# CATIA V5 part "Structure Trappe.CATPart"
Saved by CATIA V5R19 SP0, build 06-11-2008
Part number: Structure Trappe
Bounding box of the stored display mesh (mm): x -178.601 to 93.761, y -17.5 to 17.5, z -63.05 to 80.5
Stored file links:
  G:\EU_thinkMotion\CFAO_2010\St2M_groupe2\St2M_groupe2\csayed\csayed\csayed\Structure Trappe.CATPart
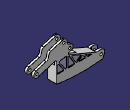
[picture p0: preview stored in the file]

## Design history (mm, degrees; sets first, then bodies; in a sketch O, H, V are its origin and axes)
Body1 (main body)
  Sketch1 on yz-plane, origin (0, 0, 0), H (0, 1, 0), V (0, 0, 1)
    line L1 (-17.5, 80.5) -> (-9.5, 80.5)
    line L2 (17.5, 80.5) -> (17.5, -63.05)
    line L3 (17.5, -63.05) -> (-17.5, -63.05)
    line L4 (-17.5, -63.05) -> (-17.5, 80.5)
    line L5 (9.5, 80.5) -> (9.5, 4.23)
    line L6 (9.5, 4.23) -> (-9.5, 4.23)
    line L7 (-9.5, 4.23) -> (-9.5, 80.5)
    line L8 (9.5, 80.5) -> (17.5, 80.5)
    distance L5 L2 = 8
    distance L7 L4 = 8
    distance L7 L5 = 19
    horizontal: L1 H, L3 H, L6 H, L8 H
    vertical: L2 V, L4 V, L5 V, L7 V
    coincidence: L1 L8
  Sketch2 on zx-plane, origin (0, 0, 0), H (-1, 0, 0), V (0, 0, 1)
    arc A1 centre (21.9628, 68.6209) radius 12 from (33.9425, 69.3181) to (16.579, 79.3454) ccw
    arc A2 centre (44.5806, 40.433) radius 12 from (43.1436, 28.5193) to (48.533, 51.7634) ccw
    point P3 (33.9425, 69.3181)
    connectcurve C1
    line L1 (-5.6287, 19.9902) -> (-5.6287, -55.0098)
    point P6 (-5.6287, -55.0098)
    line L2 (41.2327, 19.9902) -> (147.0177, -25.1156)
    point P8 (147.0177, -25.1156)
    connectcurve C2
    spline S1 through (-5.6287, -55.0098) (77.8259, -62.9391) (170.8786, -58.7018)
    spline S2 through (147.0177, -25.1156) (177.0391, -31.0056) (170.8786, -58.7018)
    point P10 (33.9425, 69.3181)
    arc A3 centre (-10.6287, 19.9902) radius 5 from (-5.6287, 19.9902) to (-12.8212, 24.4838) ccw
    line L3 (-12.8212, 24.4838) -> (-77.8369, 4.7657)
    point P14 (-77.8369, 4.7657)
    line L4 (-85.041, 28.5193) -> (-45.7585, 40.433)
    line L5 (16.579, 79.3454) -> (-28.0238, 65.8182)
    connectcurve C3
    arc A4 centre (-81.4389, 16.6425) radius 12.411 from (-85.041, 28.5193) to (-77.8369, 4.7657) ccw
    point P19 (-77.8369, 4.7657)
    point P20 (-5.6287, -55.0098)
    point P21 (147.0177, -25.1156)
    point P22 (170.8786, -58.7018)
    point P23 (170.8786, -58.7018)
    radius A3 = 5
    coincidence: P3 A1, P20 P6, P21 P8, P22 P23, P10 C1, P19 L3, P14 P19
    tangency: A3 L1, A4 L3
    parallelism: L4 L3, L5 L4
  SolidCombine1: FirstComponentProfile Sketch1, FirstComponentDirection Sketch1, SecondComponentProfile Sketch2, SecondComponentDirection Sketch2
  Sketch3 on xy-plane, origin (0, 0, 0), H (1, 0, 0), V (0, 1, 0)
    line L1 (-195.114, 9.5) -> (-154.339, 9.5)
    line L2 (-154.672, -9.5) -> (-195.114, -9.5)
    line L3 (-195.114, -9.5) -> (-195.114, 9.5)
    reference projected line E1 (-147.0177, 17.5) -> (-178.6291, 17.5) from edge [face of SolidCombine1 from Sketch1.L2 | face of SolidCombine1 from Sketch2.S2]
    reference projected line E2 (-147.0177, -17.5) -> (-178.6291, -17.5) from edge [face of SolidCombine1 from Sketch2.S2 | face of SolidCombine1 from Sketch1.L4]
    arc A1 centre (-154.672, 0.0029) radius 9.5029 from (-154.339, 9.5) to (-154.672, -9.5) cw
    distance E1 L1 = 8
    distance L2 E2 = 8
    horizontal: L1 H, L2 H
    vertical: L3 V
    tangency: A1 L2
  Pocket1: profile Sketch3, direction (0, 0, -1), through (limit type 3)
  Sketch4 on face of SolidCombine1 from Sketch1.L2, origin (0, 17.5, 0), H (-1, 0, 0), V (0, 0, 1)
    construction line L1 (147.0244, -25.1266) -> (-5.4485, -25.1266)
    line L2 (-3.7319, 3.5697) -> (-3.7319, -22.1531)
    line L3 (2.3556, 6.5289) -> (21.5313, -18.9662)
    line L4 (-1.2969, -23.5189) -> (18.1831, -23.5189)
    connectcurve C1
    connectcurve C2
    connectcurve C3
    line L5 (27.7831, -20.6237) -> (3.8883, 11.1457)
    line L6 (7.2477, 16.3099) -> (28.7693, 19.6993)
    line L7 (33.4637, 14.3104) -> (33.4637, -20.1896)
    connectcurve C4
    connectcurve C5
    connectcurve C6
    line L8 (37.4637, 14.1) -> (37.4637, -20.1896)
    line L9 (40.9432, -23.5189) -> (59.8262, -23.5189)
    point P17 (40.9432, -23.5189)
    line L10 (43.6319, 14.2097) -> (62.7173, -18.9662)
    connectcurve C7
    connectcurve C8
    connectcurve C9
    line L11 (55.4125, 9.927) -> (86.8175, -3.8821)
    line L12 (86.8175, -8.3014) -> (73.4351, -20.1896)
    line L13 (52.616, 6.6144) -> (67.2828, -18.8806)
    connectcurve C10
    connectcurve C11
    connectcurve C12
    line L14 (79.5635, -20.0958) -> (90.6743, -10.2255)
    line L15 (82.6044, -23.5189) -> (103.6044, -23.5189)
    point P29 (82.6044, -23.5189)
    line L16 (95.1278, -10.7523) -> (105.9861, -20.5122)
    connectcurve C13
    connectcurve C14
    connectcurve C15
    line L17 (102.5015, -12.0017) -> (113.7953, -22.1531)
    line L18 (103.6044, -10.7746) -> (129.4815, -22.1531)
    line L19 (115.3149, -23.5189) -> (128.881, -23.5189)
    point P37 (115.3149, -23.5189)
    connectcurve C16
    connectcurve C17
    connectcurve C18
    distance L10 L13 = 4
    distance L7 L8 = 4
    distance L3 L5 = 4
    distance L12 L14 = 4
    distance L17 L16 = 4
    horizontal: L1 H, L4 H, L9 H, L15 H, L19 H
    vertical: L2 V, L7 V, L8 V
    coincidence: P17 L4, P29 L4, P37 L17, P37 L4
    parallelism: L18 L11
  Pocket2: profile Sketch4, direction (0, -1, 0), length 3
  Mirror1: of Pocket2, about zx-plane
  Sketch5 on face of SolidCombine1 from Sketch1.L2, origin (0, 17.5, 0), H (-1, 0, 0), V (0, 0, 1)
    circle A1 centre (-81.439, 16.6425) radius 5
    point P1 (-81.439, 16.6425)
    reference projected arc E1 centre (-81.4389, 16.6425) radius 12.411 from (-85.041, 28.5193) to (-77.8369, 4.7657) ccw from edge [face of SolidCombine1 from Sketch2.A4 | face of SolidCombine1 from Sketch1.L2]
    circle A2 centre (21.9628, 68.6209) radius 5
    point P2 (21.9628, 68.6209)
    reference projected arc E2 centre (21.9628, 68.6209) radius 12 from (20.2636, 80.5) to (16.579, 79.3454) ccw from edge [face of SolidCombine1 from Sketch2.A1 | face of SolidCombine1 from Sketch1.L2]
    circle A3 centre (44.5806, 40.433) radius 5
    point P3 (44.5806, 40.433)
    reference projected arc E4 centre (44.5806, 40.433) radius 12 from (43.1436, 28.5193) to (48.533, 51.7634) ccw from edge [face of SolidCombine1 from Sketch2.A2 | face of SolidCombine1 from Sketch1.L2]
    circle A4 centre (165.0136, -40.5534) radius 5
    radius A1 = 5
    distance P1 E1 = 12.411
    distance P2 E2 = 12
    distance P3 E4 = 12
  Pocket3: profile Sketch5, direction (0, -1, 0), through (limit type 3)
